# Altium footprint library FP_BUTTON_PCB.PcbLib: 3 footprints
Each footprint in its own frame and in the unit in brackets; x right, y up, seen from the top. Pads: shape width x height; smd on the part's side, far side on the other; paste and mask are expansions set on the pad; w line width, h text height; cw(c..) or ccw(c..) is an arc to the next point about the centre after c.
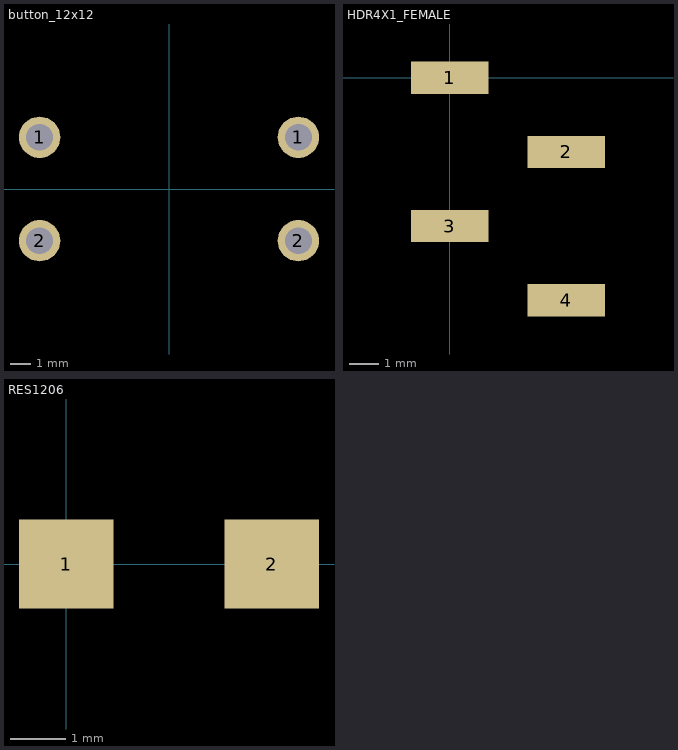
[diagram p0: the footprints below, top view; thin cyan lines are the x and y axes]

## button_12x12 [mm]
pads (4):
  round 2 hole 1.3: 1(-6.25,2.5) 1(6.25,2.5) 2(-6.25,-2.5) 2(6.25,-2.5)
3D body "bouton_12x12mm.step": height 12, standoff -3.47, extent -7.032,-6.397 7.032,6.397

## HDR4X1_FEMALE [mm]
pads (4):
  rect 2.65x1.1 smd: 1(0,0) 2(4,-2.54) 3(0,-5.08) 4(4,-7.62)
3D body "2MM-SMD-PIN-HEADER-FEMALE.STEP": height 2.33, standoff 0.01, extent -0.762,-7.703 4.738,0.337

## RES1206 [mm]
pads (2):
  rect 1.7x1.6 smd: 1(0,0) 2(3.7,0)
3D body "RC1206.stp": height 0.55, standoff 0, extent 0.253,-0.787 3.353,0.813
